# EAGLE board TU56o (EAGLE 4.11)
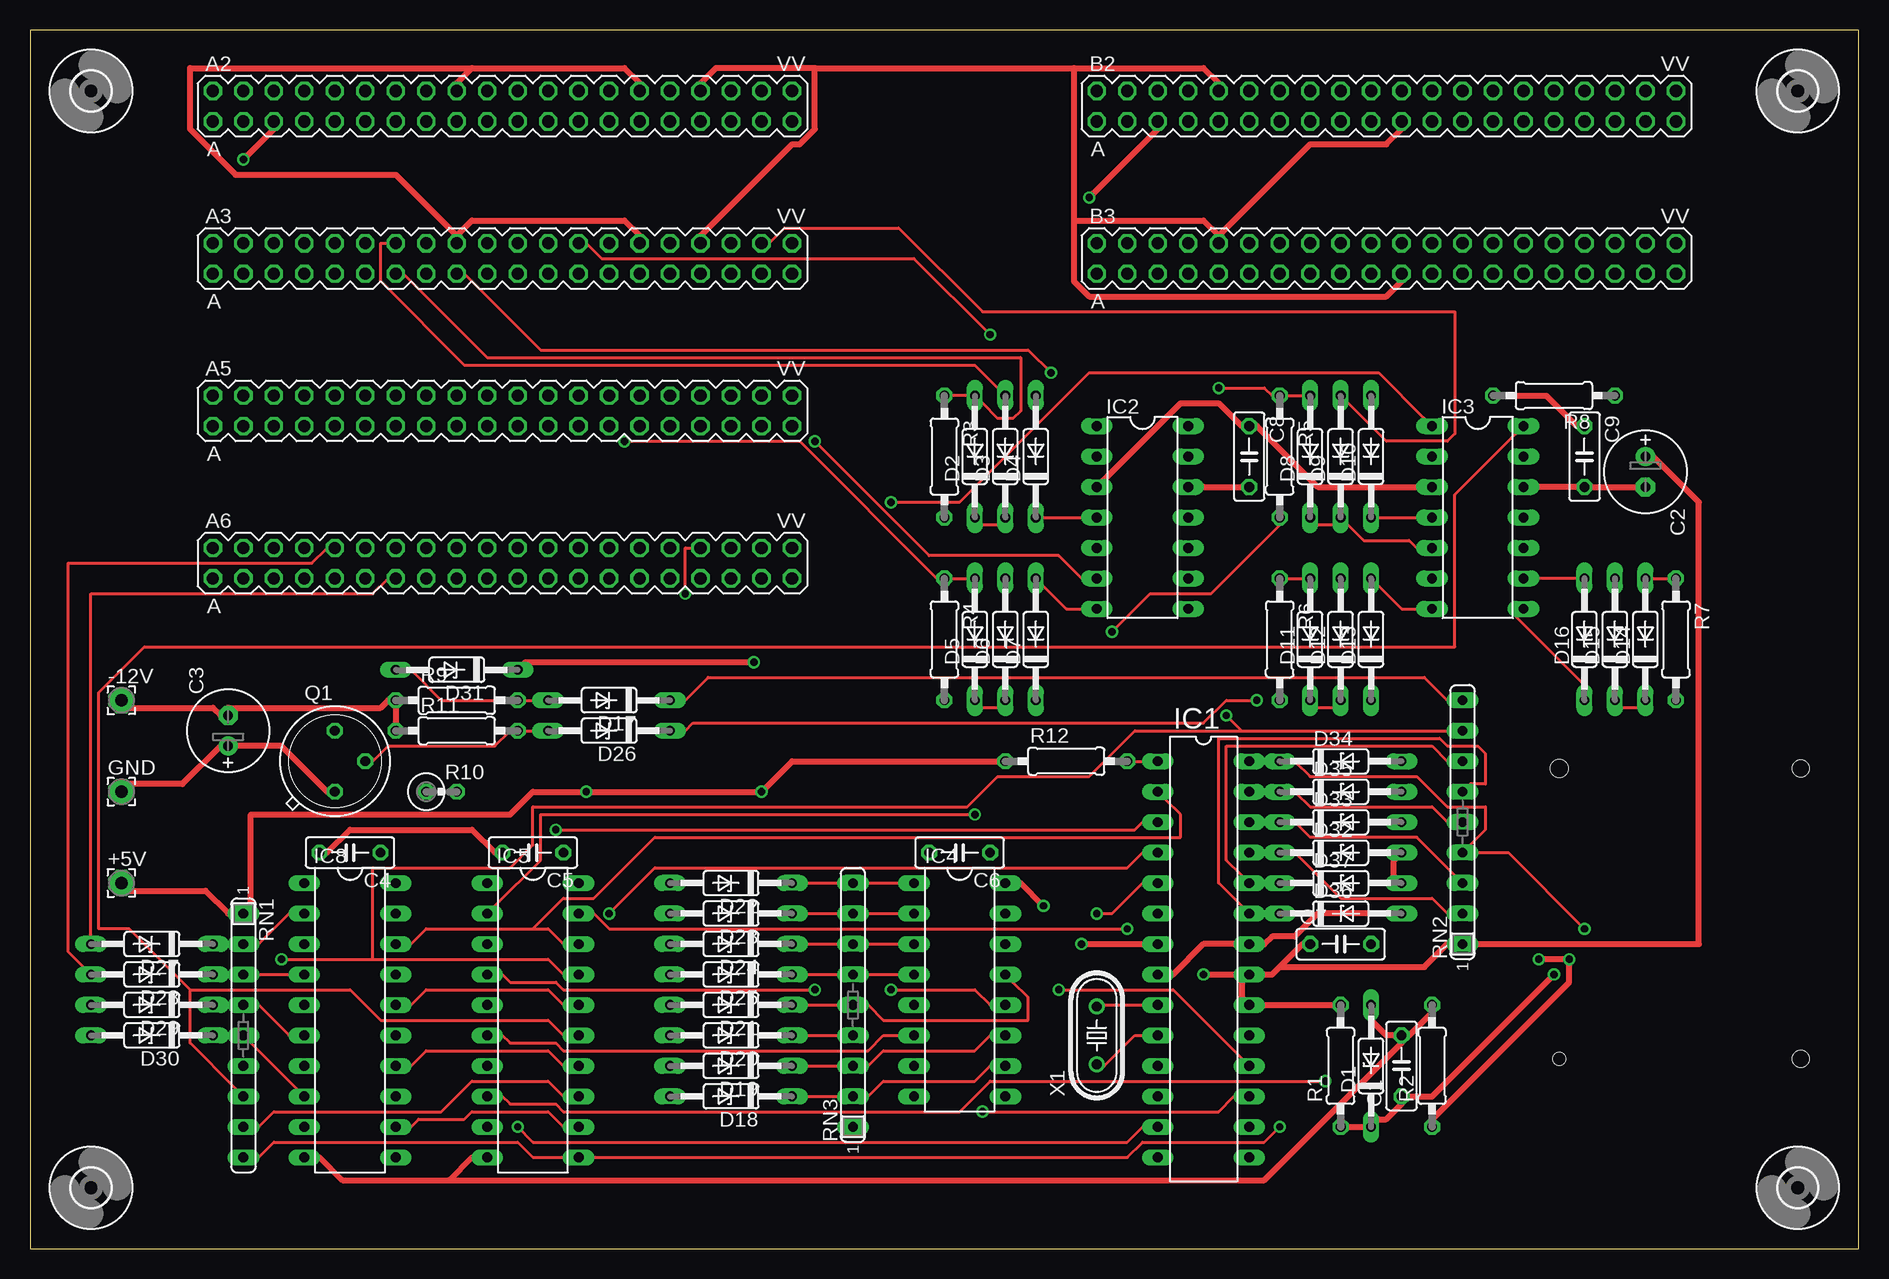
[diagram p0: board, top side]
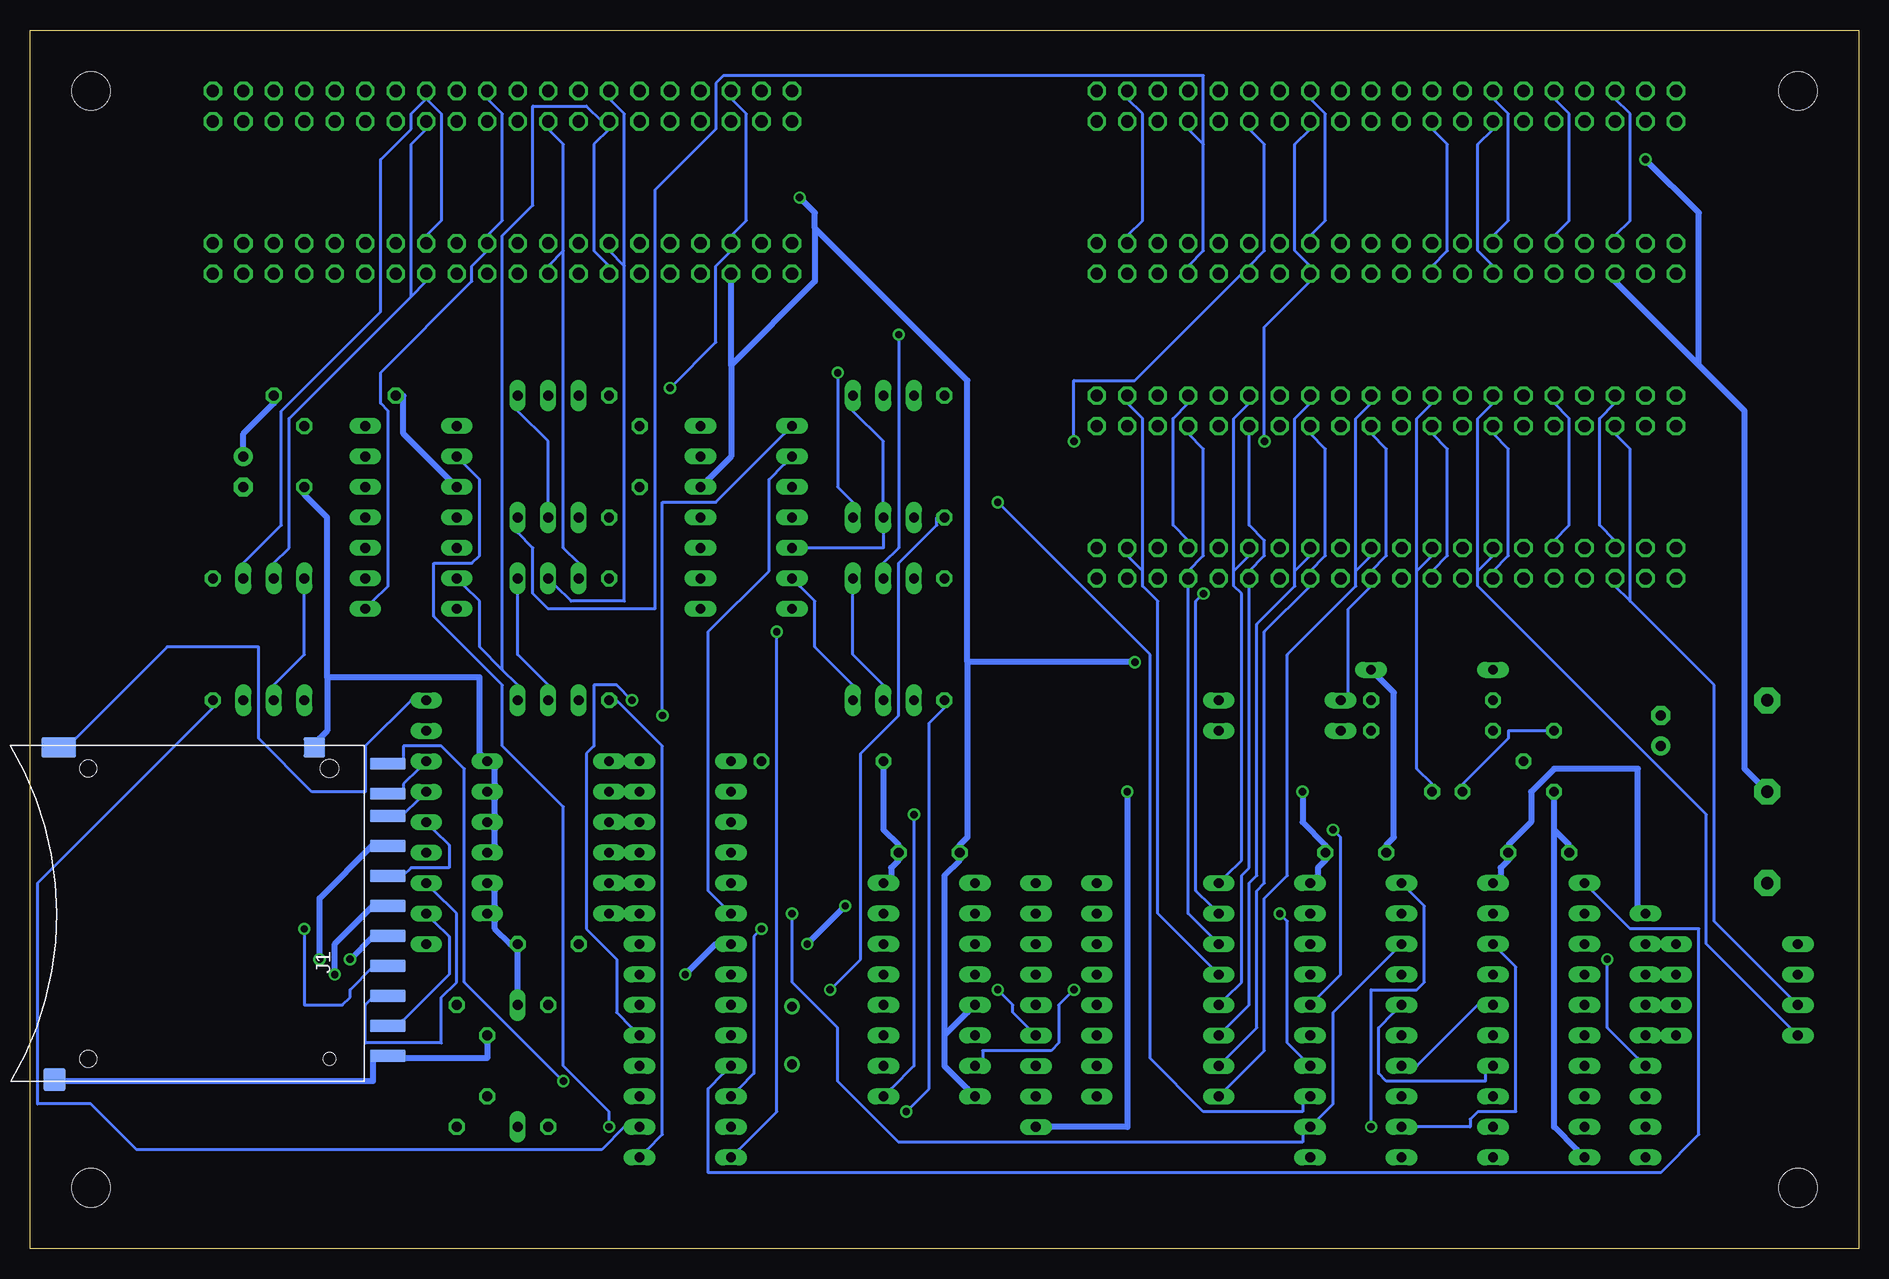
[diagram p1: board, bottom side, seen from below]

Size 152.4 x 101.6 mm. Coordinates in mm from the lower left corner, seen from the top.
Outline: 0,0 152.4,0 152.4,101.6 0,101.6 0,0
Copper layers (1*16): Top 0.035mm / dielectric 1.5mm / Bottom 0.035mm
Design rules "custompcb": minimum track width 10mil, minimum drill 24mil, track to track 8mil, track to pad 8mil, pad to pad 8mil, via to via 8mil, smd to smd 0mil, copper to edge 10mil, drill to drill 8mil, minimum pad ring 10mil, minimum via ring 8mil, stop-mask expansion 4mil, vias tented up to drill 0mil, thermal gap 10mil
Net classes: 1 Supply: width 0.508 mm, drill 0.381 mm

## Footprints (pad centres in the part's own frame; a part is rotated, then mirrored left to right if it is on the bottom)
2,15/1,0 = drill 1.016 pad 2.159 octagon: 1 0,0
DEC40PINV = drill 1.016 octagon: A -24.13,-1.27; AA 3.81,-1.27; B -24.13,1.27; BB 3.81,1.27; C -21.59,-1.27; CC 6.35,-1.27; D -21.59,1.27; DD 6.35,1.27; E -19.05,-1.27; EE 8.89,-1.27; F -19.05,1.27; FF 8.89,1.27; H -16.51,-1.27; HH 11.43,-1.27; J -16.51,1.27; JJ 11.43,1.27; K -13.97,-1.27; KK 13.97,-1.27; L -13.97,1.27; LL 13.97,1.27; M -11.43,-1.27; MM 16.51,-1.27; N -11.43,1.27; NN 16.51,1.27; P -8.89,-1.27; PP 19.05,-1.27; R -8.89,1.27; RR 19.05,1.27; S -6.35,-1.27; SS 21.59,-1.27; T -6.35,1.27; TT 21.59,1.27; U -3.81,-1.27; UU 24.13,-1.27; V -3.81,1.27; VV 24.13,1.27; W -1.27,-1.27; X -1.27,1.27; Y 1.27,-1.27; Z 1.27,1.27
C050-025X075 = drill 0.813 octagon: 1 -2.54,0; 2 2.54,0
E2,5-7 = drill 0.813 pad 1.6 round: + -1.27,0 | drill 0.813 pad 1.6 octagon: - 1.27,0
DO35Z10 = drill 0.813 long: A 5.08,0; C -5.08,0
DO35-10 = drill 0.813 long: A 5.08,0; C -5.08,0
DIL28-3 = drill 0.813 long: 1 -16.51,-3.81; 2 -13.97,-3.81; 3 -11.43,-3.81; 4 -8.89,-3.81; 5 -6.35,-3.81; 6 -3.81,-3.81; 7 -1.27,-3.81; 8 1.27,-3.81; 9 3.81,-3.81; 10 6.35,-3.81; 11 8.89,-3.81; 12 11.43,-3.81; 13 13.97,-3.81; 14 16.51,-3.81; 15 16.51,3.81; 16 13.97,3.81; 17 11.43,3.81; 18 8.89,3.81; 19 6.35,3.81; 20 3.81,3.81; 21 1.27,3.81; 22 -1.27,3.81; 23 -3.81,3.81; 24 -6.35,3.81; 25 -8.89,3.81; 26 -11.43,3.81; 27 -13.97,3.81; 28 -16.51,3.81
DIL14 = drill 0.813 long: 1 -7.62,-3.81; 2 -5.08,-3.81; 3 -2.54,-3.81; 4 0,-3.81; 5 2.54,-3.81; 6 5.08,-3.81; 7 7.62,-3.81; 8 7.62,3.81; 9 5.08,3.81; 10 2.54,3.81; 11 0,3.81; 12 -2.54,3.81; 13 -5.08,3.81; 14 -7.62,3.81
DIL16 = drill 0.813 long: 1 -8.89,-3.81; 2 -6.35,-3.81; 3 -3.81,-3.81; 4 -1.27,-3.81; 5 1.27,-3.81; 6 3.81,-3.81; 7 6.35,-3.81; 8 8.89,-3.81; 9 8.89,3.81; 10 6.35,3.81; 11 3.81,3.81; 12 1.27,3.81; 13 -1.27,3.81; 14 -3.81,3.81; 15 -6.35,3.81; 16 -8.89,3.81
DIL20 = drill 0.813 long: 1 -11.43,-3.81; 2 -8.89,-3.81; 3 -6.35,-3.81; 4 -3.81,-3.81; 5 -1.27,-3.81; 6 1.27,-3.81; 7 3.81,-3.81; 8 6.35,-3.81; 9 8.89,-3.81; 10 11.43,-3.81; 11 11.43,3.81; 12 8.89,3.81; 13 6.35,3.81; 14 3.81,3.81; 15 1.27,3.81; 16 -1.27,3.81; 17 -3.81,3.81; 18 -6.35,3.81; 19 -8.89,3.81; 20 -11.43,3.81
SCDA1A = smd 1 x 2.95: 1 -6.865,-10.76; 2 -4.365,-10.76; 3 -1.865,-10.76; 4 0.635,-10.76; 5 3.135,-10.76; 6 5.635,-10.76; 7 8.135,-10.76; 8 10,-10.76; 9 -9.365,-10.76; 10 12.5,-10.76; 13 -11.865,-10.76 | smd 1.7 x 1.8: 11 13.85,-4.65 | smd 1.7 x 2.9: 12 13.85,16.65 | smd 1.9 x 1.8: 14 -13.85,17 | hole 1.05: -12.1,-5.9 | hole 1.5: 12.1,-5.9 | hole 1.4: 12.1,14.2; -12.1,14.2
TO5 = drill 0.813 octagon: 1 0,-2.54; 2 2.54,0; 3 0,2.54
0207/10 = drill 0.813 octagon: 1 -5.08,0; 2 5.08,0
0309V = drill 0.813 octagon: 1 -1.27,0; 2 1.27,0
SIL9 = drill 0.813 long: 1 -10.16,0; 2 -7.62,0; 3 -5.08,0; 4 -2.54,0; 5 0,0; 6 2.54,0; 7 5.08,0; 8 7.62,0; 9 10.16,0
3,2 = hole 3.2: 0,0
HC49/S = drill 0.813 round: 1 -2.413,0; 2 2.413,0

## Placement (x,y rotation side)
+5V  [2,15/1,0]  7.62,30.48 0 top
-12V  [2,15/1,0]  7.62,45.72 0 top
A2  [DEC40PINV]  39.37,95.25 0 top
A3  [DEC40PINV]  39.37,82.55 0 top
A5  [DEC40PINV]  39.37,69.85 0 top
A6  [DEC40PINV]  39.37,57.15 0 top
B2  [DEC40PINV]  113.03,95.25 0 top
B3  [DEC40PINV]  113.03,82.55 0 top
C1  .01  [C050-025X075]  114.3,15.24 90 top
C2  10uf  [E2,5-7]  134.62,64.77 270 top
C3  10uf  [E2,5-7]  16.51,43.18 90 top
C4  .01  [C050-025X075]  26.67,33.02 180 top
C5  .01  [C050-025X075]  41.91,33.02 180 top
C6  .01  [C050-025X075]  77.47,33.02 180 top
C7  .01  [C050-025X075]  109.22,25.4 0 top
C8  .01  [C050-025X075]  101.6,66.04 270 top
C9  .01  [C050-025X075]  129.54,66.04 270 top
D1  3.3V  [DO35Z10]  111.76,15.24 90 top
D2  1N4148  [DO35-10]  78.74,66.04 90 top
D3  1N4148  [DO35-10]  81.28,66.04 90 top
D4  1N4148  [DO35-10]  83.82,66.04 90 top
D5  1N4148  [DO35-10]  78.74,50.8 90 top
D6  1N4148  [DO35-10]  81.28,50.8 90 top
D7  1N4148  [DO35-10]  83.82,50.8 90 top
D8  1N4148  [DO35-10]  106.68,66.04 90 top
D9  1N4148  [DO35-10]  109.22,66.04 90 top
D10  1N4148  [DO35-10]  111.76,66.04 90 top
D11  1N4148  [DO35-10]  106.68,50.8 90 top
D12  1N4148  [DO35-10]  109.22,50.8 90 top
D13  1N4148  [DO35-10]  111.76,50.8 90 top
D14  1N4148  [DO35-10]  134.62,50.8 90 top
D15  1N4148  [DO35-10]  132.08,50.8 90 top
D16  1N4148  [DO35-10]  129.54,50.8 90 top
D17  3.3V  [DO35Z10]  48.26,45.72 180 top
D18  3.3V  [DO35Z10]  58.42,12.7 180 top
D19  3.3V  [DO35Z10]  58.42,15.24 180 top
D20  3.3V  [DO35Z10]  58.42,17.78 180 top
D21  3.3V  [DO35Z10]  58.42,20.32 180 top
D22  3.3V  [DO35Z10]  58.42,30.48 180 top
D23  3.3V  [DO35Z10]  58.42,27.94 180 top
D24  3.3V  [DO35Z10]  58.42,25.4 180 top
D25  3.3V  [DO35Z10]  58.42,22.86 180 top
D26  3.3V  [DO35Z10]  48.26,43.18 180 top
D27  3.3V  [DO35Z10]  10.16,25.4 180 top
D28  3.3V  [DO35Z10]  10.16,22.86 180 top
D29  3.3V  [DO35Z10]  10.16,20.32 180 top
D30  3.3V  [DO35Z10]  10.16,17.78 180 top
D31  3.3V  [DO35Z10]  35.56,48.26 180 top
D32  3.3V  [DO35Z10]  109.22,33.02 0 top
D33  3.3V  [DO35Z10]  109.22,35.56 0 top
D34  3.3V  [DO35Z10]  109.22,40.64 0 top
D35  3.3V  [DO35Z10]  109.22,38.1 0 top
D36  3.3V  [DO35Z10]  109.22,27.94 0 top
D37  3.3V  [DO35Z10]  109.22,30.48 0 top
GND  [2,15/1,0]  7.62,38.1 0 top
IC1  ATMEGA8L-8P  [DIL28-3]  97.79,24.13 270 top
IC2  LM339N  [DIL14]  92.71,60.96 270 top
IC3  LM339N  [DIL14]  120.65,60.96 270 top
IC4  74LS148N  [DIL16]  77.47,21.59 270 top
IC5  74LS244N  [DIL20]  41.91,19.05 270 top
IC8  74LS244N  [DIL20]  26.67,19.05 270 top
J1  SDCARDMOUSER  [SCDA1A]  133.35,27.94 90 bottom
Q1  2N2905  [TO5]  25.4,40.64 0 top
R1  [0207/10]  109.22,15.24 90 top
R2  0  [0207/10]  116.84,15.24 90 top
R3  10K  [0207/10]  76.2,66.04 270 top
R4  10K  [0207/10]  76.2,50.8 270 top
R5  10K  [0207/10]  104.14,66.04 270 top
R6  10K  [0207/10]  104.14,50.8 270 top
R7  10K  [0207/10]  137.16,50.8 270 top
R8  0  [0207/10]  127,71.12 180 top
R9  10K  [0207/10]  35.56,45.72 0 top
R10  100 1/2W  [0309V]  34.29,38.1 0 top
R11  10K  [0207/10]  35.56,43.18 0 top
R12  0  [0207/10]  86.36,40.64 0 top
RN1  [SIL9]  17.78,17.78 270 top
RN2  [SIL9]  119.38,35.56 90 top
RN3  [SIL9]  68.58,20.32 90 top
U$1  [3,2]  5.08,5.08 0 top
U$2  [3,2]  5.08,96.52 0 top
U$3  [3,2]  147.32,96.52 0 top
U$4  [3,2]  147.32,5.08 0 top
X1  [HC49/S]  88.9,17.78 90 top

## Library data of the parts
+5V -12V GND = wirepad
A2 A3 A5 A6 B2 B3 = dec-con
C1-C9 R1-R12 = rcl
D1-D37 = diode
IC1 = avr
IC2 IC3 = linear
IC4 IC5 IC8 = 74xx-jameco
J1 = sdcards
Q1 = transistor-pnp
RN1-RN3 = resistor-sil
U$1-U$4 = holes
X1 = crystal

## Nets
-12V [Supply]: -12V.1 C3.- R9.1 R11.1
A: IC1.11 IC8.1
B: IC1.12 IC5.19
C: IC1.13 IC5.1
CD\: IC5.8 J1.10
CLK: D35.C IC1.27 J1.5 RN2.5
CMD: D34.C IC1.28 J1.2 RN2.4
D0: IC1.5 IC5.3 IC5.12 IC8.12
D1: IC1.4 IC5.5 IC5.14 IC8.14
D1IN: IC3.14 IC5.15 RN1.7
D1OUT: IC1.16 R7.2
D2: IC1.3 IC5.7 IC5.16 IC8.16
D2IN: IC3.1 IC5.13 RN1.8
D2OUT: IC1.15 R6.2
D3: IC1.2 IC5.9 IC5.18 IC8.18
D3IN: IC3.2 IC5.11 RN1.9
D3OUT: IC1.14 R5.2
DAT0: D36.C IC1.23 J1.7 RN2.6
DAT1: D37.C IC1.24 J1.8 RN2.7
DAT2: D32.C IC1.25 J1.9 RN2.2
DAT3: D33.C IC1.26 J1.1 RN2.3
DATA1+: B2.DD B3.DD D14.A R7.1
DATA1-: B2.CC B3.CC D15.A
DATA1CT: B2.Z B3.Z D16.C IC3.8
DATA2+: B2.U B3.U D11.A R6.1
DATA2-: B2.R B3.R D12.A
DATA2CT: B2.P B3.P D13.C IC3.6
DATA3+: B2.F B3.F D8.A R5.1
DATA3-: A2.TT A3.TT D9.A
DATA3CT: A2.MM A3.MM D10.C IC3.4
DRV0: IC4.6 IC5.6
DRV1: IC4.7 IC5.4
DRV2: IC4.9 IC5.2
DRVOK: D26.C IC1.19
FORWARD: D27.C IC8.2 RN1.2
FORWARD\: A5.P A6.P D27.A
GND [Supply]: A2.E A3.E B2.E B3.E C1.2 C2.- C3.+ C4.2 C5.2 C6.2 C7.2 C8.2 C9.2 D1.A D31.C D32.A D33.A D34.A D35.A D36.A D37.A GND.1 IC1.8 IC1.22 IC2.12 IC3.12 IC4.5 IC4.8 IC5.10 IC8.10 J1.11 J1.13 J1.14 Q1.1 R2.2
GO\: A5.F A6.F
HALT: D30.C IC8.8 RN1.5
HALT\: A5.R A6.R D30.A
J: A5.U A6.U
MARK+: A2.CC A3.CC D5.A R4.1
MARK-: A2.DD A3.DD D6.A
MARKCT: A2.HH A3.HH D7.C IC2.6
MIN: IC2.1 IC5.17 RN1.6 RN2.8
MOUT: IC1.17 R4.2
N$1: IC1.10 X1.1
N$2: IC1.9 X1.2
N$3: D18.C IC4.10 RN3.2
N$4: D19.C IC4.11 RN3.3
N$5: D20.C IC4.12 RN3.4
N$7: D2.C D3.C D4.A IC2.5
N$8: D21.C IC4.13 RN3.5
N$9: D22.C IC4.1 RN3.9
N$10: D23.C IC4.2 RN3.8
N$11: D5.C D6.C D7.A IC2.7
N$12: D8.C D9.C D10.A IC3.5
N$13: D11.C D12.C D13.A IC3.7
N$14: D14.C D15.C D16.A IC3.9
N$15: D24.C IC4.3 RN3.7
N$16: D25.C IC4.4 RN3.6
N$17: IC1.1 R12.2
N$18: Q1.3 R10.1
N$19: D26.A Q1.2 R11.2
REVERSE: D28.C IC8.4 RN1.3
REVERSE\: A5.L A6.L D28.A
SELECT: A5.V A6.V R10.2
SELECT0\: A5.Z A6.Z D18.A
SELECT1\: A5.CC A6.CC D19.A
SELECT2\: A5.DD A6.DD D20.A
SELECT3\: A5.HH A6.HH D21.A
SELECT4\: A5.JJ A6.JJ D22.A
SELECT5\: A5.NN A6.NN D23.A
SELECT6\: A5.MM A6.MM D24.A
SELECT7\: A5.TT A6.TT D25.A
SELECT\: A2.L A3.L
SHIELD1 [Supply]: A2.JJ A2.V A3.JJ A3.V
SHIELD2 [Supply]: A2.NN A3.NN B2.L B2.Y B3.L B3.Y
SKEW: A2.F A3.F
STOP: D29.C IC8.6 RN1.4
STOP\: A5.E A6.E D29.A
TIMING+: A2.P A3.P D2.A R3.1
TIMING-: A2.R A3.R D3.A
TIMINGCT: A2.U A3.U D4.C IC2.4
TIN: IC1.6 IC2.2
TOUT: IC1.18 R3.2
V+ [Supply]: C8.1 C9.1 IC2.3 IC3.3 R8.2
VCC [Supply]: +5V.1 C2.+ C4.1 C5.1 C6.1 C7.1 IC1.7 IC1.20 IC1.21 IC4.16 IC5.20 IC8.20 R1.2 R8.1 R12.1 RN1.1 RN2.1 RN3.1
VDD [Supply]: C1.1 D1.C J1.4 R1.1
VSS [Supply]: J1.3 J1.6 R2.1
WE: A5.Y A6.Y D17.A D31.A R9.2
WE\: D17.C J1.12 RN2.9

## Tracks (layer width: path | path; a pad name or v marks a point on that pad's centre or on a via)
-12V
  Top 0.508: R11.1 30.48,43.81 30.48,45.09 R9.1 29.84,45.72 29.21,45.09 16.51,45.09 C3.- 15.88,44.45 15.24,45.09 8.26,45.09 -12V.1
A
  Bottom 0.254: IC8.1 22.23,29.84 19.05,26.67 13.34,26.67 13.34,9.53 16.51,6.35 95.89,6.35 95.89,13.34 94.61,14.61 IC1.11
B  (via drill 0.61)
  Top 0.254: v91.44,26.67 48.26,26.67 46.99,27.94 IC5.19
  Bottom 0.254: v91.44,26.67 92.08,26.04 92.08,14.61 93.34,13.34 IC1.12
C  (via drill 0.61)
  Top 0.254: v40.64,10.16 41.91,8.89 91.44,8.89 92.71,10.16 IC1.13
  Bottom 0.254: v40.64,10.16 40.64,21.59 36.83,21.59 36.2,22.23 36.2,28.57 37.47,29.84 IC5.1
CD\  (via drill 0.61)
  Top 0.254: v107.95,13.97 80.01,13.97 77.47,11.43 44.45,11.43 43.81,12.06 40.01,12.06 39.37,12.7 IC5.8
  Bottom 0.254: v107.95,13.97 116.2,22.23 116.2,40.01 118.11,41.91 121.28,41.91 121.28,40.64 J1.10
CLK
  Top 0.254: RN2.5 118.11,35.56 116.84,36.83 106.68,36.83 105.41,38.1 D35.C 102.87,38.1 IC1.27
  Bottom 0.254: J1.5 121.28,31.11 120.65,31.75 117.47,31.75 117.47,33.66 118.75,34.92 RN2.5
CMD  (via drill 0.61)
  Top 0.254: IC1.28 102.87,40.64 D34.C 105.41,40.64 106.68,39.37 115.57,39.37 118.11,36.83 121.28,36.83 121.28,34.92 120.02,33.66 RN2.4 120.65,33.02 123.19,33.02 v129.54,26.67
  Bottom 0.254: v129.54,26.67 129.54,20.32 126.36,20.32 125.73,20.95 125.73,21.59 123.83,23.5 J1.2
D0  (via drill 0.61)
  Top 0.254: IC8.12 31.75,10.16 32.38,10.79 36.2,10.79 36.83,11.43 43.18,11.43 44.45,10.16 IC5.12 | v88.9,27.94 90.17,27.94 92.71,30.48 IC1.5
  Bottom 0.254: IC5.3 38.73,24.77 43.81,19.68 43.81,12.06 45.09,10.79 IC5.12 46.35,9.53 46.35,8.89 80.01,8.89 85.09,13.97 85.09,18.41 88.9,22.23 v88.9,27.94
D1  (via drill 0.61)
  Top 0.254: IC8.14 31.75,15.24 33.02,16.51 43.18,16.51 44.45,15.24 IC5.14 | v48.26,27.94 52.07,31.75 91.44,31.75 92.71,33.02 IC1.4
  Bottom 0.254: IC5.5 38.73,19.68 40.01,18.41 40.01,14.61 39.37,13.97 31.11,13.97 31.11,14.61 IC8.14 | v48.26,27.94 47.62,27.3 47.62,17.14 46.35,15.88 IC5.14
D1IN
  Top 0.254: 13.34,21.59 13.34,17.14 17.14,13.34 RN1.7 | 13.34,21.59 26.67,21.59 29.21,19.05 43.18,19.05 44.45,17.78 IC5.15 | 13.34,21.59 8.26,26.67 5.71,26.67 5.71,46.35 9.53,50.16 118.75,50.16 118.75,62.87 123.83,67.94 IC3.14
D1OUT
  Bottom 0.254: IC1.16 102.87,10.16 104.78,8.26 143.51,8.26 147.32,12.06 151.76,12.06 151.76,30.48 137.16,45.09 R7.2
D2  (via drill 0.61)
  Top 0.254: IC5.16 44.45,20.32 43.18,21.59 33.02,21.59 31.75,20.32 IC8.16 | v43.81,34.92 92.08,34.92 92.71,35.56 IC1.3
  Bottom 0.254: IC5.7 36.83,15.24 31.75,20.32 IC8.16 | v43.81,34.92 43.18,34.29 43.18,22.86 45.09,20.95 IC5.16
D2IN  (via drill 0.61)
  Top 0.254: RN1.8 19.05,10.16 20.32,11.43 34.29,11.43 36.83,13.97 43.18,13.97 44.45,12.7 IC5.13 | v71.75,62.23 77.47,62.23 88.27,73.03 112.39,73.03 116.2,69.22 IC3.1
  Bottom 0.254: v71.75,62.23 59.05,49.53 59.05,15.88 54.61,11.43 46.35,11.43 46.35,12.06 IC5.13
D2OUT
  Bottom 0.254: IC1.15 100.97,8.26 99.69,9.53 99.69,41.91 103.5,45.72 R6.2
D3
  Top 0.254: 41.91,26.67 33.02,26.67 31.75,25.4 IC8.18 | 41.91,26.67 43.18,26.67 44.45,25.4 IC5.18 | 41.91,26.67 44.45,29.21 46.99,29.21 52.07,34.29 95.89,34.29 95.89,36.2 94.61,37.47 IC1.2
  Bottom 0.254: IC5.9 36.83,10.16 32.38,10.16 32.38,10.79 31.75,11.43 28.57,11.43 28.57,23.5 29.84,24.77 IC8.18
D3IN  (via drill 0.61)
  Top 0.254: RN1.9 19.05,7.62 20.32,8.89 40.64,8.89 41.91,7.62 44.45,7.62 IC5.11 46.99,7.62 91.44,7.62 92.71,8.89 102.87,8.89 v104.14,10.16
  Bottom 0.254: v104.14,10.16 104.14,11.43 107.95,15.24 107.95,36.83 113.03,41.91 113.03,46.99 118.75,52.7 118.75,57.15 115.57,57.15 114.94,57.78 114.94,64.14 116.2,65.41 IC3.2
D3OUT  (via drill 0.61)
  Top 0.254: v90.17,51.44 93.34,54.61 98.42,54.61 104.14,60.33 R5.2
  Bottom 0.254: v90.17,51.44 90.17,11.43 93.34,8.26 IC1.14
DAT0
  Top 0.254: D36.C 102.87,27.94 IC1.23 100.97,28.57 99.06,30.48 99.06,42.55 117.47,42.55 118.11,41.91 120.65,41.91 121.28,41.27 121.28,38.73 120.02,38.73 RN2.6
  Bottom 0.254: RN2.6 120.02,37.47 121.28,36.2 J1.7
DAT1
  Top 0.254: D37.C 102.87,30.48 IC1.24 100.97,31.11 99.69,32.38 99.69,41.91 116.84,41.91 118.11,40.64 RN2.7
  Bottom 0.254: RN2.7 120.02,40.01 121.28,38.73 121.28,38.1 J1.8
DAT2
  Top 0.254: IC1.25 102.87,33.02 D32.C 105.41,33.02 109.22,29.21 116.84,29.21 118.11,27.94 RN2.2
  Bottom 0.254: RN2.2 118.75,27.3 117.47,26.04 117.47,22.86 121.28,19.05 J1.9
DAT3
  Top 0.254: IC1.26 102.87,35.56 D33.C 105.41,35.56 106.68,34.29 115.57,34.29 118.75,31.11 RN2.3
  Bottom 0.254: J1.1 123.83,20.95 124.46,20.32 124.46,17.14 118.11,17.14 118.11,20.95 116.84,22.23 116.84,27.94 118.75,29.84 RN2.3
DATA1+
  Top 0.254: D14.A 135.25,55.88 136.53,55.88 R7.1
  Bottom 0.254: 119.38,95.89 118.11,94.61 118.11,85.72 119.38,84.45 B3.DD | 119.38,95.89 B2.DD 119.38,95.89 | 119.38,95.89 120.65,94.61 120.65,93.34 123.19,90.81 123.19,78.11 131.44,69.85 131.44,60.33 134.62,57.15 D14.A
DATA1-
  Bottom 0.254: 120.65,79.38 119.38,80.64 B3.CC | 120.65,79.38 130.81,69.22 130.81,58.42 132.08,57.15 D15.A | 120.65,79.38 120.65,92.08 119.38,93.34 B2.CC
DATA1CT
  Top 0.254: D16.C 129.54,46.99 123.83,52.7 IC3.8
  Bottom 0.254: B2.Z 114.3,95.89 113.03,94.61 113.03,85.72 114.3,84.45 B3.Z 114.3,83.19 115.57,81.92 115.57,80.64 123.19,73.03 123.19,70.48 122.56,69.85 122.56,55.24 123.83,53.98 IC3.8
DATA2+
  Top 0.254: R6.1 104.78,55.88 106.05,55.88 D11.A
  Bottom 0.254: 107.95,83.19 109.22,81.92 B3.U | 107.95,83.19 107.95,92.08 109.22,93.34 B2.U | 107.95,83.19 107.95,58.42 106.68,57.15 D11.A
DATA2-
  Bottom 0.254: 102.87,81.92 102.87,53.98 107.31,53.98 108.58,55.24 D12.A | 102.87,81.92 104.14,83.19 B3.R | 102.87,81.92 102.87,94.61 104.14,95.89 B2.R
DATA2CT
  Bottom 0.254: B3.P 104.14,81.92 105.41,83.19 105.41,92.08 104.14,93.34 B2.P 104.78,93.98 106.05,95.25 110.49,95.25 110.49,87 113.03,84.45 113.03,48.26 | 113.03,48.26 114.94,50.16 114.94,53.98 116.2,55.24 IC3.6 | 113.03,48.26 111.76,46.99 D13.C
DATA3+  (via drill 0.61)
  Top 0.254: D8.A 106.05,71.12 104.78,71.12 R5.1 103.5,71.12 102.87,71.75 v99.06,71.75
  Bottom 0.254: B2.F 93.98,95.89 92.71,94.61 92.71,85.72 93.98,84.45 B3.F 93.98,83.19 95.25,81.92 95.25,75.56 v99.06,71.75
DATA3-
  Top 0.254: D9.A 109.86,70.48 113.03,67.31 118.11,67.31 118.75,67.94 118.75,78.11 79.38,78.11 72.39,85.09 62.87,85.09 61.59,83.82 A3.TT
  Bottom 0.254: A2.TT 60.96,95.89 59.69,94.61 59.69,85.72 60.96,84.45 A3.TT
DATA3CT
  Top 0.254: D10.C 112.39,60.96 115.57,60.96 IC3.4
  Bottom 0.254: 54.61,92.08 54.61,83.19 55.88,81.92 A3.MM | 54.61,92.08 55.88,93.34 A2.MM | 54.61,92.08 54.61,97.79 94.61,97.79 95.25,97.16 95.25,93.34 100.33,88.27 100.33,53.34 109.22,53.34 110.49,54.61 110.49,58.42 111.76,59.69 D10.C
DRV0
  Top 0.254: IC5.6 39.37,17.78 40.01,17.14 43.81,17.14 44.45,16.51 69.85,16.51 71.12,17.78 72.39,17.78 IC4.6
DRV1  (via drill 0.61)
  Top 0.254: v65.41,21.59 44.45,21.59 43.81,22.23 40.01,22.23 39.37,22.86 IC5.4
  Bottom 0.254: v65.41,21.59 66.67,20.32 66.67,17.14 67.31,16.51 73.03,16.51 73.03,15.88 IC4.7
DRV2  (via drill 0.61)
  Top 0.254: v78.74,36.2 42.55,36.2 42.55,32.38 38.73,28.57 IC5.2
  Bottom 0.254: v78.74,36.2 78.74,15.24 80.64,13.34 IC4.9
DRVOK  (via drill 0.61)
  Top 0.254: v102.23,45.72 99.69,45.72 97.79,43.81 55.24,43.81 54.61,43.18 D26.C
  Bottom 0.254: v102.23,45.72 103.5,46.99 105.41,46.99 105.41,41.91 106.05,41.27 106.05,26.67 103.5,24.13 103.5,19.68 102.23,18.41 IC1.19
FORWARD
  Top 0.254: D27.C 16.51,25.4 RN1.2 19.05,25.4 21.59,27.94 IC8.2
FORWARD\
  Top 0.254: D27.A 5.08,26.04 5.08,54.61 28.57,54.61 29.84,55.88 A6.P
  Bottom 0.254: A5.P 30.48,67.94 29.21,66.67 29.21,57.78 30.48,56.52 A6.P
GND  (via drill 0.61)
  Top 0.508: IC2.12 97.79,63.5 100.97,63.5 C8.2 | v88.27,87.63 93.98,93.34 B2.E | IC3.12 125.73,63.5 128.91,63.5 C9.2 130.18,63.5 133.99,63.5 C2.- | IC1.8 95.25,22.86 97.79,25.4 100.33,25.4 IC1.22 102.87,25.4 103.5,26.04 105.41,26.04 107.31,27.94 113.03,27.94 D36.A | D1.A 111.76,19.05 113.03,17.78 113.67,17.78 C1.2 | R2.2 116.84,19.68 114.94,17.78 C1.2 | D32.A 113.67,32.38 113.67,31.11 D37.A | 34.92,5.71 26.04,5.71 24.13,7.62 IC8.10 | 34.92,5.71 36.83,7.62 IC5.10 | v17.78,90.81 20.32,93.34 A2.E | GND.1 8.26,38.73 12.7,38.73 15.88,41.91 C3.+ 17.14,41.91 20.95,41.91 24.77,38.1 Q1.1 | C5.2 38.73,33.02 36.83,34.92 26.67,34.92 24.77,33.02 C4.2 | 34.92,5.71 102.87,5.71 114.3,17.14 C1.2 | v60.33,48.9 41.27,48.9 D31.C
  Bottom 0.508: 76.2,17.78 76.2,15.24 74.3,13.34 IC4.8 | 76.2,17.78 74.3,19.68 IC4.5 | 76.2,17.78 76.2,31.11 74.93,32.38 C6.2 74.93,33.66 74.3,34.29 74.3,48.9 | 93.98,73.66 93.98,66.04 95.89,64.14 IC2.12 | 93.98,73.66 93.98,80.64 B3.E | v88.27,87.63 87,86.36 87,85.09 | 87,85.09 87,80.64 93.98,73.66 | 74.3,48.9 74.3,72.39 87,85.09 | 127.64,47.62 127.64,60.96 129.54,62.87 C9.2 | 127.64,47.62 127.64,43.18 128.27,42.55 J1.11 | J1.14 149.86,13.97 123.83,13.97 123.83,15.88 J1.13 121.28,15.88 114.3,15.88 114.3,17.14 C1.2 | D37.A 113.67,29.84 113.67,28.57 D36.A 113.67,27.3 113.67,26.67 112.39,25.4 C7.2 111.76,24.77 111.76,21.59 D1.A | D32.A 113.67,33.66 113.67,34.92 D33.A 113.67,36.2 113.67,37.47 D35.A 113.67,38.73 113.67,40.01 D34.A 114.94,41.27 114.94,47.62 127.64,47.62 | C5.2 39.37,33.66 38.73,34.29 38.73,46.35 40.01,47.62 D31.C | 25.4,34.92 24.13,33.66 C4.2 | 25.4,34.92 25.4,37.47 Q1.1 | 13.34,73.66 9.53,69.85 9.53,40.01 8.26,38.73 GND.1 | 13.34,73.66 20.32,80.64 A3.E | v17.78,90.81 13.34,86.36 13.34,73.66 | 25.4,34.92 25.4,10.16 23.5,8.26 IC8.10 | v60.33,48.9 74.3,48.9
GO\
  Bottom 0.254: A6.F 20.32,59.05 21.59,60.33 21.59,69.22 20.32,70.48 A5.F
HALT
  Top 0.254: D30.C 16.51,17.78 RN1.5 18.41,17.14 22.23,13.34 IC8.8
HALT\
  Bottom 0.254: 31.75,56.52 31.75,55.24 12.7,36.2 12.7,25.4 5.71,18.41 D30.A | 31.75,56.52 30.48,57.78 A6.R | 31.75,56.52 31.75,69.22 30.48,70.48 A5.R
J
  Bottom 0.254: A6.U 35.56,56.52 34.29,57.78 34.29,66.67 35.56,67.94 A5.U
MARK+  (via drill 0.61)
  Top 0.254: D5.A 78.11,55.88 76.83,55.88 R4.1 75.56,55.88 64.14,67.31 v49.53,67.31
  Bottom 0.254: A2.CC 45.72,93.34 46.99,92.08 46.99,83.19 45.72,81.92 A3.CC 45.72,80.64 49.53,76.83 v49.53,67.31
MARK-  (via drill 0.61)
  Top 0.254: v80.01,76.2 73.66,82.55 47.62,82.55 46.35,83.82 A3.DD
  Bottom 0.254: v80.01,76.2 80.01,58.42 81.28,57.15 D6.A | A2.DD 45.72,95.89 44.45,94.61 44.45,85.72 45.72,84.45 A3.DD
MARKCT  (via drill 0.61)
  Top 0.254: v65.41,67.31 74.93,57.78 85.72,57.78 87.63,55.88 IC2.6
  Bottom 0.254: A2.HH 50.8,93.34 49.53,92.08 49.53,83.19 50.8,81.92 A3.HH 51.44,81.28 60.33,72.39 65.41,72.39 v65.41,67.31 | D7.C 83.82,46.99 87,50.16 87,53.98 88.27,55.24 IC2.6
MIN  (via drill 0.61)
  Top 0.254: 28.57,24.13 43.18,24.13 44.45,22.86 IC5.17 | v20.95,24.13 28.57,24.13 | 100.97,43.18 v99.69,44.45 | 100.97,43.18 118.11,43.18 RN2.8 | 28.57,24.13 28.57,31.75 40.01,31.75 41.91,33.66 41.91,36.83 78.11,36.83 80.64,39.37 88.27,39.37 92.08,43.18 100.97,43.18
  Bottom 0.254: v20.95,24.13 20.95,18.41 18.41,15.88 RN1.6 | v99.69,44.45 99.69,62.23 95.25,62.23 89.53,67.94 IC2.1
MOUT  (via drill 0.61)
  Top 0.254: v79.38,11.43 99.06,11.43 100.33,12.7 IC1.17
  Bottom 0.254: v79.38,11.43 77.47,13.34 77.47,43.81 76.2,45.09 R4.2
N$1
  Top 0.254: X1.1 89.53,15.24 92.08,17.78 92.71,17.78 IC1.10
N$2
  Top 0.254: X1.2 89.53,20.32 92.71,20.32 IC1.9
N$3
  Top 0.254: D18.C 64.77,12.7 67.31,12.7 RN3.2 69.85,12.7 71.12,13.97 78.74,13.97 80.01,15.24 IC4.10
N$4
  Top 0.254: D19.C 64.77,15.24 67.31,15.24 RN3.3 69.85,15.24 71.12,16.51 78.74,16.51 80.01,17.78 IC4.11
N$5  (via drill 0.61)
  Top 0.254: D20.C 64.77,17.78 67.31,17.78 RN3.4 | v71.75,21.59 78.74,21.59 80.01,20.32 IC4.12
  Bottom 0.254: v71.75,21.59 70.48,20.32 70.48,19.68 69.22,18.41 RN3.4
N$7
  Top 0.254: D2.C 79.38,60.33 80.64,60.33 D3.C
  Bottom 0.254: IC2.5 87.63,58.42 81.28,58.42 81.28,59.69 D3.C 81.28,62.23 81.28,67.31 83.82,69.85 D4.A
N$8
  Top 0.254: D21.C 64.77,20.32 67.31,20.32 RN3.5 69.85,20.32 71.12,19.05 83.19,19.05 83.19,20.95 81.92,22.23 IC4.13
N$9
  Top 0.254: D22.C 64.77,30.48 67.31,30.48 RN3.9 69.85,30.48 72.39,30.48 IC4.1
N$10
  Top 0.254: D23.C 64.77,27.94 67.31,27.94 RN3.8 69.85,27.94 72.39,27.94 IC4.2
N$11
  Top 0.254: D5.C 79.38,45.09 80.64,45.09 D6.C | D7.A 84.45,55.24 86.36,53.34 87.63,53.34 IC2.7
  Bottom 0.254: D6.C 81.28,46.99 83.82,49.53 83.82,54.61 D7.A
N$12
  Top 0.254: D8.C 107.31,60.33 108.58,60.33 D9.C 109.86,60.33 111.12,59.05 114.94,59.05 115.57,58.42 IC3.5
  Bottom 0.254: D10.A 111.76,69.85 109.22,67.31 109.22,62.23 D9.C
N$13
  Top 0.254: D11.C 107.31,45.09 108.58,45.09 D12.C | D13.A 112.39,55.24 114.3,53.34 115.57,53.34 IC3.7
  Bottom 0.254: D12.C 109.22,46.99 111.76,49.53 111.76,54.61 D13.A
N$14
  Top 0.254: D15.C 132.72,45.09 133.99,45.09 D14.C | IC3.9 125.73,55.88 128.91,55.88 D16.A
  Bottom 0.254: D15.C 132.08,46.99 129.54,49.53 129.54,54.61 D16.A
N$15
  Top 0.254: D24.C 64.77,25.4 67.31,25.4 RN3.7 69.85,25.4 72.39,25.4 IC4.3
N$16
  Top 0.254: D25.C 64.77,22.86 67.31,22.86 RN3.6 69.85,22.86 72.39,22.86 IC4.4
N$17
  Top 0.254: R12.2 92.08,40.64 92.71,40.64 IC1.1
N$18
  Bottom 0.254: Q1.3 26.04,43.18 29.21,43.18 29.21,42.55 33.02,38.73 R10.1
N$19
  Top 0.254: Q1.2 28.57,40.64 29.84,41.91 38.73,41.91 40.01,43.18 R11.2 41.27,43.18 41.91,43.18 D26.A
REVERSE
  Top 0.254: D28.C 16.51,22.86 RN1.3 19.05,22.86 21.59,22.86 IC8.4
REVERSE\
  Top 0.254: D28.A 4.45,23.5 3.17,24.77 3.17,57.15 23.5,57.15 24.77,58.42 A6.L
  Bottom 0.254: A5.L 25.4,70.48 24.13,69.22 24.13,60.33 25.4,59.05 A6.L
SELECT
  Bottom 0.254: 36.83,56.52 36.83,40.01 35.56,38.73 R10.2 | 36.83,56.52 35.56,57.78 A6.V | 36.83,56.52 36.83,69.22 35.56,70.48 A5.V
SELECT0\
  Bottom 0.254: 41.91,56.52 41.91,55.24 47.62,49.53 47.62,31.11 49.53,29.21 49.53,16.51 52.7,13.34 D18.A | 41.91,56.52 40.64,57.78 A6.Z | 41.91,56.52 41.91,69.22 40.64,70.48 A5.Z
SELECT1\
  Bottom 0.254: D19.A 52.7,15.88 50.16,18.41 50.16,29.84 49.53,30.48 49.53,51.44 45.72,55.24 A6.CC 45.72,56.52 44.45,57.78 44.45,66.67 45.72,67.94 A5.CC
SELECT2\
  Bottom 0.254: 46.99,56.52 46.99,55.24 50.16,52.07 50.16,31.11 50.8,30.48 50.8,20.32 52.7,18.41 D20.A | 46.99,56.52 45.72,57.78 A6.DD | 46.99,56.52 46.99,69.22 45.72,70.48 A5.DD
SELECT3\
  Bottom 0.254: D21.A 52.7,20.95 51.44,22.23 51.44,31.11 50.8,31.75 50.8,55.24 A6.HH 50.8,56.52 49.53,57.78 49.53,59.05 50.8,60.33 50.8,67.94 A5.HH
SELECT4\
  Bottom 0.254: 52.07,56.52 52.07,55.24 51.44,54.61 51.44,32.38 52.7,31.11 D22.A | 52.07,56.52 50.8,57.78 A6.JJ | 52.07,56.52 52.07,69.22 50.8,70.48 A5.JJ
SELECT5\  (via drill 0.61)
  Top 0.254: v54.61,54.61 54.61,58.42 55.24,58.42 A6.NN
  Bottom 0.254: v54.61,54.61 55.24,53.98 55.24,29.84 53.98,28.57 D23.A | A5.NN 55.88,70.48 57.15,69.22 57.15,60.33 55.88,59.05 A6.NN
SELECT6\
  Bottom 0.254: D24.A 53.98,26.04 55.88,27.94 55.88,55.24 A6.MM 55.88,56.52 54.61,57.78 54.61,66.67 55.88,67.94 A5.MM
SELECT7\
  Bottom 0.254: 59.69,56.52 59.69,55.24 58.42,53.98 58.42,27.94 53.98,23.5 D25.A | 59.69,56.52 60.96,57.78 A6.TT | 59.69,56.52 59.69,69.22 60.96,70.48 A5.TT
SELECT\
  Bottom 0.254: A3.L 25.4,84.45 24.13,85.72 24.13,94.61 25.4,95.89 A2.L
SHIELD1
  Top 0.508: 35.56,84.45 36.83,85.72 49.53,85.72 50.8,84.45 A3.JJ | 35.56,84.45 A3.V 35.56,84.45 | 36.83,98.42 35.56,97.16 A2.V | 36.83,98.42 49.53,98.42 50.8,97.16 A2.JJ | 35.56,84.45 30.48,89.53 17.14,89.53 13.34,93.34 13.34,98.42 36.83,98.42
SHIELD2
  Top 0.508: 99.06,84.45 106.68,92.08 113.03,92.08 114.3,93.34 B2.Y | 99.06,84.45 B3.L 99.06,84.45 | 65.41,98.42 65.41,93.34 64.14,92.08 63.5,92.08 55.88,84.45 A3.NN | 65.41,98.42 57.15,98.42 55.88,97.16 A2.NN | 65.41,98.42 87,98.42 | 87,98.42 97.79,98.42 99.06,97.16 B2.L | 87,98.42 87,85.72 | 87,85.72 87,80.64 88.27,79.38 113.03,79.38 114.3,80.64 B3.Y | 99.06,84.45 97.79,85.72 87,85.72
SKEW
  Bottom 0.254: A3.F 20.32,84.45 19.05,85.72 19.05,94.61 20.32,95.89 A2.F
STOP
  Top 0.254: D29.C 16.51,20.32 RN1.4 19.05,20.32 21.59,17.78 IC8.6
STOP\
  Bottom 0.254: 19.05,53.98 20.32,55.24 A6.E | 19.05,53.98 12.06,46.99 12.06,27.3 5.71,20.95 D29.A | 19.05,53.98 19.05,66.67 20.32,67.94 A5.E
TIMING+
  Top 0.254: R3.1 76.83,71.12 78.11,71.12 D2.A 79.38,70.48 80.64,69.22 81.92,69.22 82.55,69.85 82.55,74.3 38.1,74.3 31.11,81.28 A3.P
  Bottom 0.254: A3.P 30.48,81.92 31.75,83.19 31.75,92.08 30.48,93.34 A2.P
TIMING-
  Top 0.254: D3.A 80.64,71.75 78.74,73.66 36.2,73.66 29.21,80.64 29.21,83.82 29.84,83.82 A3.R
  Bottom 0.254: A2.R 30.48,95.89 29.21,94.61 29.21,85.72 30.48,84.45 A3.R
TIMINGCT  (via drill 0.61)
  Top 0.254: D4.C 84.45,60.96 87.63,60.96 IC2.4 | v85.09,73.03 83.19,74.93 42.55,74.93 36.2,81.28 A3.U
  Bottom 0.254: A3.U 35.56,81.92 34.29,83.19 34.29,92.08 35.56,93.34 A2.U | v85.09,73.03 85.09,63.5 83.82,62.23 D4.C
TIN
  Bottom 0.254: IC1.6 94.61,28.57 95.89,29.84 95.89,51.44 90.81,56.52 90.81,64.14 89.53,65.41 IC2.2
TOUT  (via drill 0.61)
  Top 0.254: v85.72,21.59 95.25,21.59 100.97,15.88 IC1.18
  Bottom 0.254: v85.72,21.59 83.19,24.13 83.19,41.27 80.01,44.45 80.01,57.15 76.83,60.33 76.83,60.96 R3.2
V+
  Top 0.508: IC2.3 89.53,64.14 95.89,70.48 99.06,70.48 100.97,68.58 C8.1 102.23,68.58 107.31,63.5 115.57,63.5 IC3.3 | C9.1 128.91,68.58 126.36,71.12 122.56,71.12 R8.2
  Bottom 0.508: IC3.3 117.47,64.14 121.28,67.94 121.28,71.12 R8.2
VCC  (via drill 0.61)
  Top 0.508: IC1.21 100.97,22.23 100.97,20.95 IC1.20 102.87,20.32 108.58,20.32 R1.2 | v97.79,22.86 100.33,22.86 IC1.21 | 104.14,23.5 103.5,22.86 102.87,22.86 IC1.21 | 104.14,23.5 106.05,25.4 C7.1 | 104.14,23.5 116.2,23.5 118.11,25.4 RN2.1 120.65,25.4 139.06,25.4 139.06,62.23 135.25,66.04 C2.+ | +5V.1 8.26,29.84 14.61,29.84 16.51,27.94 RN1.1 18.41,28.57 18.41,36.2 40.01,36.2 41.91,38.1 v46.35,38.1 v60.96,38.1 63.5,40.64 80.64,40.64 R12.1 | v87.63,25.4 92.71,25.4 IC1.7 | v84.45,28.57 82.55,30.48 IC4.16
  Bottom 0.508: R8.1 132.08,70.48 134.62,67.94 134.62,66.67 C2.+ | v97.79,22.86 95.25,25.4 IC1.7 | IC8.20 29.84,31.11 29.84,31.75 29.21,32.38 C4.1 29.21,33.66 27.3,35.56 27.3,38.1 25.4,40.01 18.41,40.01 18.41,28.57 RN1.1 | IC4.16 80.64,31.11 80.64,31.75 80.01,32.38 C6.1 80.01,33.66 81.28,34.92 81.28,40.01 R12.1 | IC5.20 45.09,31.11 45.09,31.75 44.45,32.38 C5.1 44.45,33.66 46.35,35.56 v46.35,38.1 | v60.96,38.1 60.96,10.16 67.31,10.16 RN3.1 | v84.45,28.57 v87.63,25.4
VDD  (via drill 0.61)
  Top 0.508: R1.1 109.86,10.16 111.12,10.16 D1.C 112.39,10.79 113.03,10.79 114.3,12.06 C1.1 114.94,12.7 116.84,12.7 v127,22.86
  Bottom 0.508: v127,22.86 127,25.4 123.83,28.57 J1.4
VSS  (via drill 0.61)
  Top 0.508: v125.73,24.13 v128.27,24.13 128.27,22.23 116.84,10.79 R2.1
  Bottom 0.508: v125.73,24.13 123.83,26.04 J1.3 | v128.27,24.13 128.27,29.21 123.83,33.66 J1.6
WE
  Top 0.254: D31.A 31.75,48.26 34.29,45.72 40.01,45.72 R9.2 41.27,45.72 41.91,45.72 D17.A
  Bottom 0.254: D17.A 42.55,46.35 42.55,53.34 40.64,55.24 A6.Y 40.64,56.52 39.37,57.78 39.37,66.67 40.64,67.94 A5.Y
WE\
  Top 0.254: D17.C 54.61,45.72 56.52,47.62 116.2,47.62 118.11,45.72 RN2.9
  Bottom 0.254: J1.12 148.59,42.55 140.97,50.16 133.35,50.16 133.35,42.55 128.91,38.1 124.46,38.1 124.46,41.91 120.65,45.72 RN2.9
